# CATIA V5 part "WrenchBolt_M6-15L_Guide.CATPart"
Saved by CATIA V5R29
Part number: WrenchBolt_M6-15L_Guide
Source: Unknown
Bounding box of the stored display mesh (mm): x -5.11 to 5.11, y -5.11 to 5.11, z -15 to 6
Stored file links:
  C:\가치같이\SmartFactory_BoxErectorConveyor\Boxing(under)\WrenchBolt_M6-15L_Guide.CATPart
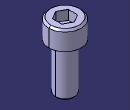
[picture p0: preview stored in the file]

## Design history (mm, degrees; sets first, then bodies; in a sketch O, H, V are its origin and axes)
Body1 (main body)
  Solid1 "PartBody": solid without history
